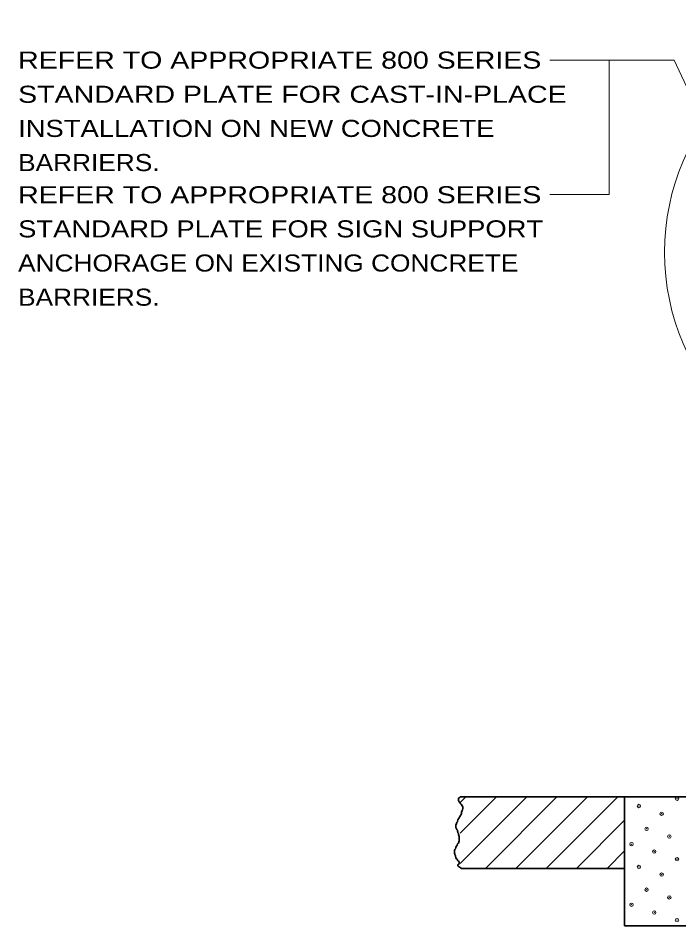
# Model space of a CAD drawing. Extents: x 5332.5 to 5339, y 1824.9 to 1835.1.
# Drawn here: x 5332.891 to 5335.213, y 1828 to 1831.189 of the extents above; entities that cross this region are included whole.
import ezdxf

# ---------------------------------------------------------------- set-up
doc = ezdxf.new("R2010")
doc.units = 0
doc.header["$LTSCALE"] = 0.024
doc.header["$PDMODE"] = 32
doc.header["$PDSIZE"] = 0.012
for name, color, linetype, lineweight in [('1', 7, 'Continuous', 35), ('10', 7, 'Continuous', 13), ('12', 7, 'Continuous', 53), ('6', 7, 'Continuous', 13)]:
    doc.layers.add(name, color=color, linetype=linetype, lineweight=lineweight)

msp = doc.modelspace()

# ---------------------------------------------------------------- linework, layer by layer
at = {"layer": '1'}
for p, q in [((5335.023, 1828.453), (5334.445, 1828.453)), ((5335.023, 1828), (5335.023, 1828.453)), ((5335.023, 1828.201), (5335.023, 1828.453))]:
    msp.add_line(p, q, dxfattribs=at)
for points in [[(5335.023, 1828), (5336.935, 1828), (5336.935, 1828.604)], [(5335.023, 1828.453), (5335.325, 1828.453), (5335.325, 1828.604)], [(5334.445, 1828.453), (5334.442, 1828.451), (5334.441, 1828.449), (5334.439, 1828.449), (5334.439, 1828.44), (5334.44, 1828.438), (5334.441, 1828.437), (5334.441, 1828.435), (5334.444, 1828.434), (5334.445, 1828.432), (5334.445, 1828.43), (5334.447, 1828.428), (5334.449, 1828.427), (5334.45, 1828.425), (5334.452, 1828.422), (5334.453, 1828.42), (5334.454, 1828.417), (5334.454, 1828.412), (5334.453, 1828.408), (5334.452, 1828.405), (5334.45, 1828.4), (5334.449, 1828.394), (5334.444, 1828.384), (5334.441, 1828.38), (5334.439, 1828.376), (5334.437, 1828.372), (5334.435, 1828.368), (5334.435, 1828.365), (5334.433, 1828.363), (5334.432, 1828.36), (5334.43, 1828.354), (5334.43, 1828.345), (5334.431, 1828.343), (5334.433, 1828.339), (5334.435, 1828.336), (5334.435, 1828.333), (5334.437, 1828.33), (5334.437, 1828.327), (5334.439, 1828.324), (5334.439, 1828.321)], [(5334.439, 1828.321), (5334.44, 1828.317), (5334.441, 1828.314), (5334.441, 1828.311), (5334.441, 1828.309), (5334.441, 1828.302), (5334.441, 1828.299), (5334.439, 1828.291), (5334.436, 1828.288), (5334.434, 1828.283), (5334.431, 1828.279), (5334.43, 1828.275), (5334.428, 1828.271), (5334.426, 1828.268), (5334.425, 1828.265), (5334.425, 1828.255), (5334.426, 1828.252), (5334.426, 1828.25), (5334.427, 1828.248), (5334.428, 1828.246), (5334.429, 1828.243), (5334.43, 1828.241), (5334.43, 1828.239), (5334.432, 1828.236), (5334.433, 1828.235), (5334.436, 1828.231), (5334.437, 1828.229), (5334.439, 1828.228), (5334.44, 1828.226), (5334.441, 1828.224), (5334.441, 1828.22), (5334.44, 1828.218), (5334.439, 1828.216), (5334.438, 1828.215), (5334.437, 1828.213), (5334.437, 1828.212), (5334.438, 1828.21), (5334.441, 1828.207), (5334.442, 1828.206), (5334.445, 1828.206)], [(5334.445, 1828.206), (5334.445, 1828.205), (5334.446, 1828.204), (5334.448, 1828.203), (5334.448, 1828.202), (5334.449, 1828.201), (5335.023, 1828.201)]]:
    msp.add_lwpolyline(points, dxfattribs=at)
at = {"layer": '10'}
for p, q in [((5335.197, 1831.042), (5334.76, 1831.042)), ((5334.968, 1831.042), (5334.968, 1830.57)), ((5335.24, 1830.949), (5335.197, 1831.042)), ((5334.968, 1830.57), (5334.76, 1830.57))]:
    msp.add_line(p, q, dxfattribs=at)
msp.add_circle((5335.9865, 1830.3665), 0.823, dxfattribs=at)
at = {"layer": '6'}
for p, q in [((5334.445, 1828.219), (5334.679, 1828.453)), ((5334.445, 1828.326), (5334.572, 1828.453)), ((5334.445, 1828.433), (5334.465, 1828.453)), ((5334.534, 1828.201), (5334.785, 1828.453)), ((5334.641, 1828.201), (5334.892, 1828.453)), ((5334.747, 1828.201), (5334.999, 1828.453)), ((5334.854, 1828.201), (5335.023, 1828.371)), ((5334.961, 1828.201), (5335.023, 1828.264))]:
    msp.add_line(p, q, dxfattribs=at)
for p in [(5335.207, 1828.447), (5335.073, 1828.421), (5335.153, 1828.394), (5335.1, 1828.341), (5335.18, 1828.314), (5335.047, 1828.287), (5335.127, 1828.261), (5335.073, 1828.207), (5335.207, 1828.234), (5335.153, 1828.18), (5335.1, 1828.127), (5335.18, 1828.1), (5335.047, 1828.074), (5335.127, 1828.047), (5335.207, 1828.02)]:
    msp.add_point(p, dxfattribs=at)

# ---------------------------------------------------------------- texts
at = {"layer": '12'}
for s, width, p in [('REFER TO APPROPRIATE 800 SERIES', 1.25, (5332.891, 1831.012)), ('STANDARD PLATE FOR CAST-IN-PLACE', 1.25, (5332.891, 1830.892)), ('INSTALLATION ON NEW CONCRETE', 1.2, (5332.891, 1830.772)), ('BARRIERS.', 1.15, (5332.891, 1830.652)), ('REFER TO APPROPRIATE 800 SERIES', 1.25, (5332.891, 1830.539)), ('STANDARD PLATE FOR SIGN SUPPORT', 1.2, (5332.891, 1830.419)), ('ANCHORAGE ON EXISTING CONCRETE', 1.15, (5332.891, 1830.299)), ('BARRIERS.', 1.15, (5332.891, 1830.179))]:
    msp.add_text(s, height=0.06, dxfattribs=dict(at, width=width)).set_placement(p)

doc.saveas('drawing.dxf')
